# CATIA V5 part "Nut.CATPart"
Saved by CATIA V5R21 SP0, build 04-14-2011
Part number: nut
Bounding box of the stored display mesh (mm): x -13.856 to 13.856, y 0 to 9, z -12 to 12
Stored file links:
  D:\CATIA V5R21 E-RESOURCES\CATIA-V5R21\catia-v5r21-Prts\c12_catia_v5r21_prt\c12_catia_v5r21figr_12-53\Nut.CATPart
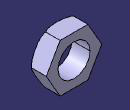
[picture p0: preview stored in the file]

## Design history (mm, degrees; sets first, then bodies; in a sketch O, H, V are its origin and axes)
Body1 (main body)
  Sketch1 on zx-plane, origin (0, 0, 0), H (-1, 0, 0), V (0, 0, 1)
    circle A1 centre (0, 0) radius 8
    construction circle A2 centre (0, 0) radius 12
    point P1 (-6.9282, -12)
    point P2 (6.9282, -12)
    point P3 (13.8564, 0)
    point P4 (6.9282, 12)
    point P5 (-6.9282, 12)
    point P6 (-13.8564, 0)
    point P7 (0, -12)
    line L1 (-6.9282, -12) -> (6.9282, -12)
    line L2 (6.9282, -12) -> (13.8564, 0)
    line L3 (13.8564, 0) -> (6.9282, 12)
    line L4 (6.9282, 12) -> (-6.9282, 12)
    line L5 (-6.9282, 12) -> (-13.8564, 0)
    line L6 (-13.8564, 0) -> (-6.9282, -12)
    construction line L7 (0, 0) -> (0, -12)
    construction circle A3 centre (0, 0) radius 13.8564
    construction arc A4 centre (-6.9282, 12) radius 13.8564 from (6.9282, 12) to (-13.8564, 0) cw
    construction arc A5 centre (6.9282, -12) radius 13.8564 from (13.8564, 0) to (-6.9282, -12) ccw
    radius A1 = 8
    radius A2 = 12
    coincidence: P7 A2, A3 P1, A3 P2, A3 P3, A3 P4, A3 P5, A3 P6, A4 O, A5 O
    vertical: L7 V
    midpoint: P7 L1
    parallelism: L1 L4
  Pad1: profile Sketch1, direction (0, 1, 0), length 9
  Sketch2 on xy-plane, origin (0, 0, 0), H (1, 0, 0), V (0, 1, 0)
    projected line E1 (10.7061, 0) -> (13.8564, 0) from edge of Pad1
    point P1 (13.8564, 0)
    projected line E2 (13.8564, 0) -> (13.8564, 1.8188) from edge of Pad1
    point P2 (13.8564, 0)
    arc A1 centre (10.7061, 3.6376) radius 3.6376 from (10.7061, 0) to (13.8564, 1.8188) ccw
    coincidence: P1 P2
    tangency: A1 E1
  Groove1: profile Sketch2, axis axis of face of Pad1, angle 360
